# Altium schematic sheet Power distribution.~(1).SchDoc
size A3; SheetNumber: 7; SheetTotal: 8
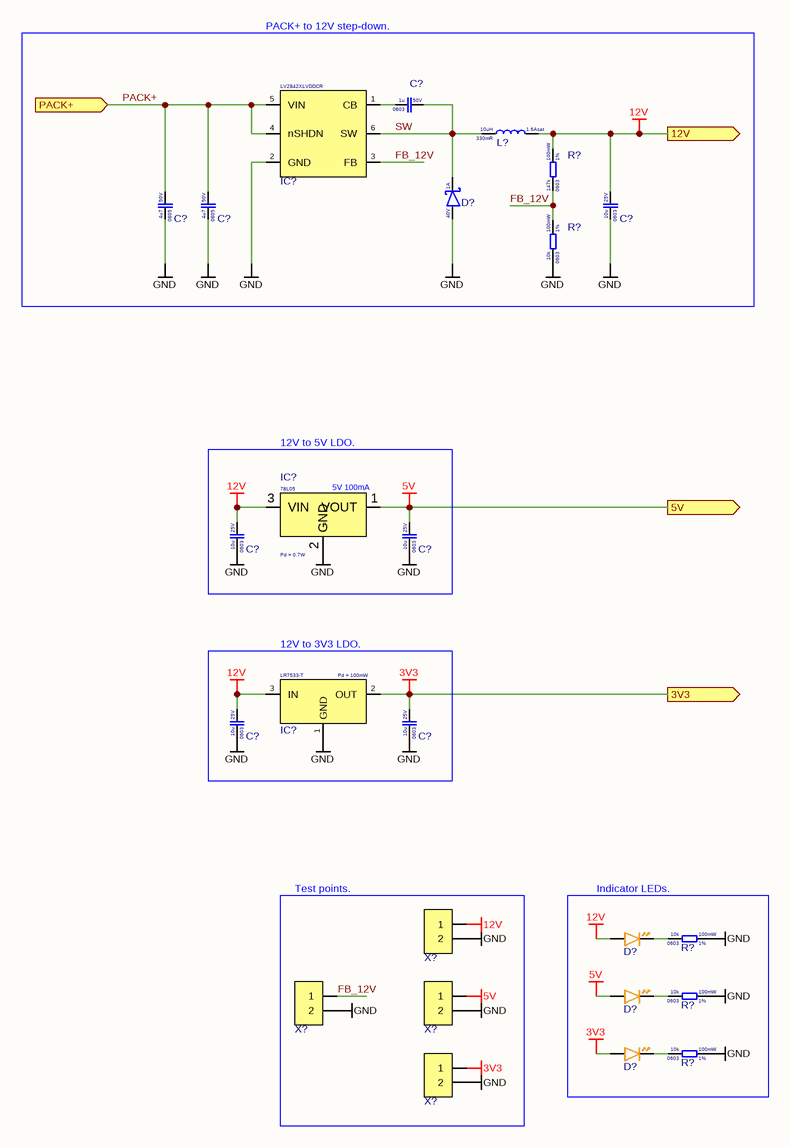
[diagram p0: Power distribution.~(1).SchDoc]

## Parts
(Parts that share a designator on the sheet are numbered #1, #2 ... from top to bottom, then left to right.)
C?#1  Voltage Rating: 50V  Case Code (Imperial): 0603  Capacitance: 1u  [CAP 0603]  (hidden comment: CL10A105KB8NNNC)
C?#2  Voltage Rating: 50V  Case Code (Imperial): 0805  Capacitance: 4u7  [Cap_0805]  (hidden comment: CL21A475KBQNNNE)
C?#3  Voltage Rating: 50V  Case Code (Imperial): 0805  Capacitance: 4u7  [Cap_0805]  (hidden comment: CL21A475KBQNNNE)
C?#4  Voltage Rating: 25V  Case Code (Imperial): 0603  Capacitance: 10u  [CAP 0603]  (hidden comment: CL10A106MA8NRNC)
C?#5  Voltage Rating: 25V  Case Code (Imperial): 0603  Capacitance: 10u  [CAP 0603]  (hidden comment: CL10A106MA8NRNC)
C?#6  Voltage Rating: 25V  Case Code (Imperial): 0603  Capacitance: 10u  [CAP 0603]  (hidden comment: CL10A106MA8NRNC)
C?#7  Voltage Rating: 25V  Case Code (Imperial): 0603  Capacitance: 10u  [CAP 0603]  (hidden comment: CL10A106MA8NRNC)
C?#8  Voltage Rating: 25V  Case Code (Imperial): 0603  Capacitance: 10u  [CAP 0603]  (hidden comment: CL10A106MA8NRNC)
D?#1  Forward Current: 1A  Reverse Voltage: 40V  [SOD-323]  (hidden comment: 1N5819WS)
D?#2  XL-1608UOC-06  [DIODE_0603_ORANGE]  (value not drawn)
D?#3  XL-1608UOC-06  [DIODE_0603_ORANGE]  (value not drawn)
D?#4  XL-1608UOC-06  [DIODE_0603_ORANGE]  (value not drawn)
IC?#1  LV2842XLVDDCR  [SOT-23-6]
IC?#2  Pd = 0.7W  [SOT-89-3]
IC?#3  Pd = 100mW  [SOT-23 123]
L?  Resistance: 330mR  Saturation current: 1.6Asat  Inductance: 10uH  [IND 1008]  (hidden comment: FTC252012S100MBCA)
R?#1  Resistance Tolerance: 1%  Resistance: 147k  Power Rating: 100mW  Case Code (Imperial): 0603  [RES_0603]  (hidden comment: 0603WAF1473T5E)
R?#2  Resistance Tolerance: 1%  Resistance: 10k  Power Rating: 100mW  Case Code (Imperial): 0603  [RES_0603]  (hidden comment: 0603WAF1002T5E)
R?#3  Resistance Tolerance: 1%  Resistance: 10k  Power Rating: 100mW  Case Code (Imperial): 0603  [RES_0603]  (hidden comment: 0603WAF1002T5E)
R?#4  Resistance Tolerance: 1%  Resistance: 10k  Power Rating: 100mW  Case Code (Imperial): 0603  [RES_0603]  (hidden comment: 0603WAF1002T5E)
R?#5  Resistance Tolerance: 1%  Resistance: 10k  Power Rating: 100mW  Case Code (Imperial): 0603  [RES_0603]  (hidden comment: 0603WAF1002T5E)
X?#1  ZX-PZ1.27-1-2PZZ  [Pin header 1x2 1.27mmP THT Vertical]  (value not drawn)
X?#2  ZX-PZ1.27-1-2PZZ  [Pin header 1x2 1.27mmP THT Vertical]  (value not drawn)
X?#3  ZX-PZ1.27-1-2PZZ  [Pin header 1x2 1.27mmP THT Vertical]  (value not drawn)
X?#4  ZX-PZ1.27-1-2PZZ  [Pin header 1x2 1.27mmP THT Vertical]  (value not drawn)

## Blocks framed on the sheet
PACK+ to 12V step-down.: C?#1-C?#4 D?#1 IC?#1 L? R?#1 R?#2
12V to 5V LDO.: C?#5 C?#6 IC?#2
12V to 3V3 LDO.: C?#7 C?#8 IC?#3
Test points.: X?#1-X?#4
Indicator LEDs.: D?#2-D?#4 R?#3-R?#5

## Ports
3V3 (out, see CHARGER[4C], USB PD[5B]), 5V (out, see CHARGER[4C], USB PD[2B]), 12V (out, see CHARGER[4C], Charger BQ25756[8A]), PACK+ (in, see CHARGER[3C], BMS[8A], Charger BQ25756[1A], CHARGER[1B])

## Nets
3V3: C?#8.2 D?#4.A IC?#3.2(OUT) X?#4.1 ; port 3V3
5V: C?#6.2 D?#3.A IC?#2.1(VOUT) X?#3.1 ; port 5V
12V: C?#4.2 C?#5.2 C?#7.2 D?#2.A IC?#2.3(VIN) IC?#3.3(IN) L?.2 R?#1.2 X?#1.1 ; port 12V
GND: C?#2.1 C?#3.1 C?#4.1 C?#5.1 C?#6.1 C?#7.1 C?#8.1 D?#1.A IC?#1.2(GND) IC?#2.2(GND) IC?#3.1(GND) R?#2.1 R?#3.2 R?#4.2 R?#5.2 X?#1.2 X?#2.2 X?#3.2 X?#4.2
FB_12V: IC?#1.3(FB) R?#1.1 R?#2.2 X?#2.1
PACK+: C?#2.2 C?#3.2 IC?#1.4(nSHDN) IC?#1.5(VIN) ; port PACK+
SW: C?#1.2 D?#1.K IC?#1.6(SW) L?.1
NetC?#1_1: C?#1.1 IC?#1.1(CB)
NetD?#2_K: D?#2.K R?#3.1
NetD?#3_K: D?#3.K R?#4.1
NetD?#4_K: D?#4.K R?#5.1

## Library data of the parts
C?#1 = CL10A105KB8NNNC: Cap 1uF 50V 0603 X5R; Manufacturer: Samsung
C?#2 C?#3 = CL21A475KBQNNNE: Cap 4.7uF 50V 0805 X5R; Manufacturer: Samsung
C?#4-C?#8 = CL10A106MA8NRNC: Cap 10uF 25V 0603 X5R; Manufacturer: Samsung
D?#1 = 1N5819WS: Schottky 40V 1A 600mVf SOD-323; Manufacturer: Guangdong Hottech
D?#2-D?#4 = XL-1608UOC-06: LED Orange 0603 20mA; Manufacturer: XINGLIGHT
IC?#1 = LV2842XLVDDCR: Step-down converter 4~40Vin 600mAout Adjustible SOT23-6; Manufacturer: Texas Instruments
IC?#2 = 78L05: LDO 5V 100mA 30Vin; Manufacturer: UMW
IC?#3 = LR7533-T: LDO 24Vin 3.3Vout fixed; Manufacturer: LR
L? = FTC252012S100MBCA: Inductor 10uH 1.6Asat 330mR; Manufacturer: cjiang
R?#1 = 0603WAF1473T5E: Res 147k 0603 1% 100mW 75V; Manufacturer: Uni-Royal
R?#2-R?#5 = 0603WAF1002T5E: Res 10k 0603 1% 100mW 75V; Manufacturer: Uni-Royal
X?#1-X?#4 = ZX-PZ1.27-1-2PZZ: Pin header 1x2 1.27mmP THT Vertical; Manufacturer: Megastar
